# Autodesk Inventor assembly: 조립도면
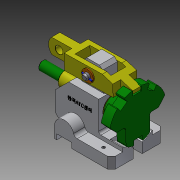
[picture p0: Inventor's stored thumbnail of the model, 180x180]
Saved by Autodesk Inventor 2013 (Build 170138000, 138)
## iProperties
Created: 2016-11
Part Number: 조립도면
Document SubType Name: Assembly
Designer: default
Author: default
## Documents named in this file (8)
- C:\Documents and Settings\default\바탕 화면\조립도면.iam
- C:\Documents and Settings\default\바탕 화면\부품1.ipt
- C:\Documents and Settings\default\바탕 화면\461108V1022\부시.ipt
- C:\Documents and Settings\default\바탕 화면\461108V1022\분할축.ipt
- C:\Documents and Settings\default\바탕 화면\461108V1022\분할대.ipt
- C:\Documents and Settings\default\바탕 화면\461108V1022\클레비스핀.ipt
- C:\Documents and Settings\default\바탕 화면\461108V1022\와셔.ipt
- C:\Documents and Settings\default\바탕 화면\461108V1022\원통형핀.ipt
